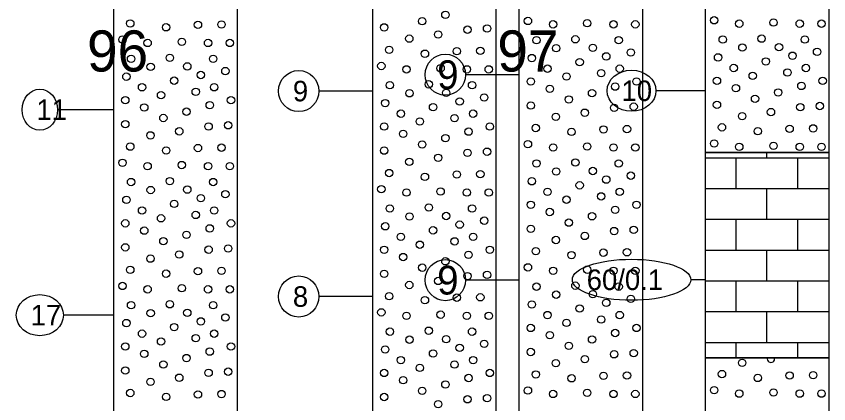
# Model space of a CAD drawing. Extents: x 2345490 to 2436403, y 465165 to 573888.
# Drawn here: x 2389896.8 to 2390094.5, y 557685.8 to 557780.1 of the extents above; entities that cross this region are included whole.
import ezdxf

# ---------------------------------------------------------------- set-up
doc = ezdxf.new("R2010")
doc.units = 0
for name, color, linetype in [('Old_Level_1', 7, 'Continuous'), ('Prop Road Sect_ Boring - Material (Outline)', 7, 'Continuous'), ('Prop Road Sect_ Boring - Peripheral (SPT Oval + Leader)', 7, 'Continuous'), ('Prop Road Sect_ Boring - Peripheral (SPT Tx)', 7, 'Continuous')]:
    doc.layers.add(name, color=color, linetype=linetype)

msp = doc.modelspace()

# ---------------------------------------------------------------- linework, layer by layer
at = {"layer": 'Prop Road Sect_ Boring - Material (Outline)'}
for p, q in [((2390064.5425, 557745.6425), (2390094.51256, 557745.6425)), ((2390072.01251, 557738.14968), (2390072.01251, 557745.6425)), ((2390079.51253, 557745.6425), (2390079.51253, 557746.92666)), ((2390087.01254, 557738.14968), (2390087.01254, 557745.6425)), ((2390094.5275, 557745.6425), (2390094.5425, 557745.6425)), ((2390064.5425, 557738.14968), (2390094.51256, 557738.14968)), ((2390079.51253, 557730.65687), (2390079.51253, 557738.14968)), ((2390094.5275, 557738.14968), (2390094.5425, 557738.14968)), ((2390064.5425, 557730.65687), (2390094.51256, 557730.65687)), ((2390072.01251, 557726.91166), (2390072.01251, 557730.65687)), ((2390087.01254, 557726.91166), (2390087.01254, 557730.65687)), ((2390094.5275, 557730.65687), (2390094.5425, 557730.65687)), ((2390072.01251, 557723.15031), (2390072.01251, 557726.89672)), ((2390087.01254, 557723.15031), (2390087.01254, 557726.89672)), ((2390064.5425, 557723.15031), (2390094.51256, 557723.15031)), ((2390079.51253, 557715.6575), (2390079.51253, 557723.15031)), ((2390094.5275, 557723.15031), (2390094.5425, 557723.15031)), ((2390064.5425, 557715.6575), (2390094.51256, 557715.6575)), ((2390072.01251, 557708.16468), (2390072.01251, 557715.6575)), ((2390087.01254, 557708.16468), (2390087.01254, 557715.6575)), ((2390094.5275, 557715.6575), (2390094.5425, 557715.6575)), ((2390064.5425, 557708.16468), (2390094.51256, 557708.16468)), ((2390079.51253, 557700.67187), (2390079.51253, 557708.16468)), ((2390094.5275, 557708.16468), (2390094.5425, 557708.16468)), ((2390064.5425, 557700.67187), (2390094.51256, 557700.67187)), ((2390072.01251, 557696.92666), (2390072.01251, 557700.67187)), ((2390087.01254, 557696.92666), (2390087.01254, 557700.67187)), ((2390094.5275, 557700.67187), (2390094.5425, 557700.67187))]:
    msp.add_line(p, q, dxfattribs=at)
for points in [[(2389983.5425, 557845.85303), (2390013.5425, 557845.85303), (2390013.5425, 557645.85303), (2389983.5425, 557645.85303)], [(2389920.5425, 557842.314), (2389950.5425, 557842.314), (2389950.5425, 557592.314), (2389920.5425, 557592.314)], [(2390064.5425, 557811.92666), (2390094.5425, 557811.92666), (2390094.5425, 557746.92666), (2390064.5425, 557746.92666)], [(2390019.2285, 557796.83938), (2390049.2285, 557796.83938), (2390049.2285, 557596.83938), (2390019.2285, 557596.83938)], [(2390064.5425, 557746.92666), (2390094.5425, 557746.92666), (2390094.5425, 557696.92666), (2390064.5425, 557696.92666)], [(2390064.5425, 557696.92666), (2390094.5425, 557696.92666), (2390094.5425, 557596.92666), (2390064.5425, 557596.92666)]]:
    msp.add_lwpolyline(points, close=True, dxfattribs=at)
for centre in [(2390001.24558, 557780.39438), (2389924.55055, 557778.32033), (2389941.02058, 557777.97533), (2389946.75059, 557778.06533), (2389995.60556, 557778.84938), (2390021.33154, 557778.9157), (2390027.45156, 557778.0907), (2390035.76157, 557778.3607), (2390042.16659, 557778.0907), (2390047.4766, 557778.0907), (2390066.64554, 557779.07798), (2390072.76556, 557778.25298), (2390081.07557, 557778.52298), (2390087.48059, 557778.25298), (2390092.7906, 557778.25298), (2389933.26557, 557777.37533), (2389986.33555, 557777.34937), (2390006.61559, 557776.79437), (2390011.3856, 557777.07937), (2389922.64554, 557774.39032), (2389992.45556, 557774.61937), (2389999.47557, 557775.60937), (2390023.42542, 557774.22536), (2390032.87723, 557774.45721), (2390043.42155, 557774.22536), (2390068.73942, 557774.38764), (2390078.19123, 557774.6195), (2390088.73555, 557774.38764), (2389928.76556, 557773.56532), (2389937.07557, 557773.83532), (2389943.48059, 557773.56532), (2389948.7906, 557773.56532), (2390028.20437, 557772.27605), (2390037.11379, 557772.38214), (2390073.51837, 557772.43833), (2390082.42779, 557772.54443), (2389987.55055, 557771.88936), (2389996.26557, 557770.94436), (2390004.02058, 557771.54436), (2390009.75059, 557771.63436), (2390040.39658, 557770.29074), (2390046.38159, 557771.25074), (2390067.60555, 557770.04803), (2390085.71058, 557770.45303), (2390091.69559, 557771.41303), (2389924.73942, 557769.69998), (2389934.19123, 557769.93184), (2389944.73555, 557769.69998), (2389985.64554, 557767.95935), (2390022.29155, 557769.88574), (2390033.92653, 557768.90402), (2390079.24053, 557769.06631), (2389929.51837, 557767.75067), (2389938.42779, 557767.85677), (2389947.69559, 557766.72537), (2389991.76556, 557767.13435), (2390000.07557, 557767.40435), (2390006.48059, 557767.13435), (2390011.7906, 557767.13435), (2390026.10155, 557767.30574), (2390039.16658, 557766.21073), (2390043.66659, 557767.30574), (2390071.41555, 557767.46802), (2390084.48058, 557766.37302), (2390088.98059, 557767.46802), (2389923.60555, 557765.36037), (2389935.24053, 557764.37865), (2389941.71058, 557765.76537), (2390022.02155, 557764.17073), (2390030.72156, 557765.40073), (2390047.7466, 557764.17073), (2390067.33555, 557764.33301), (2390076.03556, 557765.56302), (2390093.0606, 557764.33301), (2389927.41555, 557762.78036), (2389944.98059, 557762.78036), (2389987.73942, 557763.26901), (2389997.19123, 557763.50087), (2390007.73555, 557763.26901), (2390026.64156, 557762.40073), (2390042.57159, 557762.94073), (2390071.95556, 557762.56301), (2390087.88559, 557763.10301), (2389932.03556, 557760.87536), (2389940.48058, 557761.68536), (2389992.51837, 557761.3197), (2390001.42779, 557761.4258), (2390010.69559, 557760.2944), (2390036.93158, 557761.36572), (2390082.24558, 557761.52801), (2389923.33555, 557759.64535), (2389943.88559, 557758.41535), (2389949.0606, 557759.64535), (2389986.60555, 557758.9294), (2390004.71058, 557759.3344), (2390022.02155, 557758.32072), (2390031.29156, 557759.82072), (2390067.33555, 557758.483), (2390076.60556, 557759.98301), (2390092.3856, 557758.213), (2389927.95556, 557757.87535), (2389938.24558, 557756.84035), (2389990.41555, 557756.34939), (2389998.24053, 557757.94768), (2390007.98059, 557756.34939), (2390035.16157, 557756.58071), (2390042.30159, 557757.76572), (2390047.0716, 557758.05072), (2390080.47557, 557756.743), (2390087.61559, 557757.928), (2389932.60556, 557755.29535), (2389995.03556, 557754.44439), (2390003.48058, 557755.25439), (2390028.14156, 557755.59071), (2390073.45556, 557755.753), (2389923.33555, 557753.79534), (2389943.61559, 557753.24034), (2389948.3856, 557753.52534), (2389986.33555, 557753.21438), (2390012.0606, 557753.21438), (2390023.23655, 557752.86071), (2390039.70658, 557752.51571), (2390045.43659, 557752.60571), (2390068.55055, 557753.02299), (2390085.02058, 557752.67799), (2390090.75059, 557752.76799), (2389929.45556, 557751.06534), (2389936.47557, 557752.05534), (2389990.95556, 557751.44438), (2390001.24558, 557750.40938), (2390006.88559, 557751.98438), (2390031.95157, 557751.9157), (2390077.26557, 557752.07799), (2389924.55055, 557748.33533), (2389995.60556, 557748.86438), (2390021.33154, 557748.9307), (2390035.76157, 557748.3757), (2390066.64554, 557749.09298), (2390072.76556, 557748.26798), (2390081.07557, 557748.53798), (2390087.48059, 557748.26798), (2390092.7906, 557748.26798), (2389933.26557, 557747.39033), (2389941.02058, 557747.99033), (2389946.75059, 557748.08033), (2389986.33555, 557747.36437), (2390006.61559, 557746.80937), (2390011.3856, 557747.09437), (2390027.45156, 557748.1057), (2390042.16659, 557748.1057), (2390047.4766, 557748.1057), (2389922.64554, 557744.40532), (2389992.45556, 557744.63437), (2389999.47557, 557745.62437), (2390023.42542, 557744.24036), (2390032.87723, 557744.47221), (2390043.42155, 557744.24036), (2389928.76556, 557743.58032), (2389937.07557, 557743.85032), (2389943.48059, 557743.58032), (2389948.7906, 557743.58032), (2390028.20437, 557742.29105), (2390037.11379, 557742.39714), (2389987.55055, 557741.90436), (2389996.26557, 557740.95936), (2390004.02058, 557741.55936), (2390009.75059, 557741.64936), (2390040.39658, 557740.30574), (2390046.38159, 557741.26574), (2389924.73942, 557739.71498), (2389934.19123, 557739.94684), (2389944.73555, 557739.71498), (2390022.29155, 557739.90074), (2390033.92653, 557738.91902), (2389929.51837, 557737.76567), (2389938.42779, 557737.87177), (2389947.69559, 557736.74037), (2389985.64554, 557737.97435), (2389991.76556, 557737.14935), (2390000.07557, 557737.41935), (2390006.48059, 557737.14935), (2390011.7906, 557737.14935), (2390026.10155, 557737.32074), (2390043.66659, 557737.32074), (2389923.60555, 557735.37537), (2389935.24053, 557734.39365), (2389941.71058, 557735.78037), (2390030.72156, 557735.41573), (2390039.16658, 557736.22573), (2389927.41555, 557732.79536), (2389944.98059, 557732.79536), (2389987.73942, 557733.28401), (2389997.19123, 557733.51587), (2390007.73555, 557733.28401), (2390022.02155, 557734.18573), (2390026.64156, 557732.41573), (2390042.57159, 557732.95573), (2390047.7466, 557734.18573), (2389932.03556, 557730.89036), (2389940.48058, 557731.70036), (2389992.51837, 557731.3347), (2390001.42779, 557731.4408), (2390036.93158, 557731.38072), (2389923.33555, 557729.66035), (2389943.88559, 557728.43035), (2389949.0606, 557729.66035), (2389986.60555, 557728.9444), (2390004.71058, 557729.3494), (2390010.69559, 557730.3094), (2390031.29156, 557729.83572), (2389927.95556, 557727.89035), (2389938.24558, 557726.85535), (2389998.24053, 557727.96268), (2390022.02155, 557728.33572), (2390035.16157, 557726.59571), (2390042.30159, 557727.78072), (2390047.0716, 557728.06572), (2389932.60556, 557725.31035), (2389990.41555, 557726.36439), (2389995.03556, 557724.45939), (2390003.48058, 557725.26939), (2390007.98059, 557726.36439), (2390028.14156, 557725.60571), (2389923.33555, 557723.81034), (2389943.61559, 557723.25534), (2389948.3856, 557723.54034), (2389986.33555, 557723.22938), (2390012.0606, 557723.22938), (2390023.23655, 557722.87571), (2390039.70658, 557722.53071), (2390045.43659, 557722.62071), (2389929.45556, 557721.08034), (2389936.47557, 557722.07034), (2389990.95556, 557721.45938), (2390006.88559, 557721.99938), (2390031.95157, 557721.9307), (2389995.60556, 557718.87938), (2390001.24558, 557720.42438), (2390021.33154, 557718.9457), (2389924.55055, 557718.35033), (2389933.26557, 557717.40533), (2389941.02058, 557718.00533), (2389946.75059, 557718.09533), (2389986.33555, 557717.37937), (2390006.61559, 557716.82437), (2390011.3856, 557717.10937), (2390027.45156, 557718.1207), (2390035.76157, 557718.3907), (2390042.16659, 557718.1207), (2390047.4766, 557718.1207), (2389992.45556, 557714.64937), (2389999.47557, 557715.63937), (2389922.64554, 557714.42032), (2389928.76556, 557713.59532), (2389937.07557, 557713.86532), (2389943.48059, 557713.59532), (2389948.7906, 557713.59532), (2390023.42542, 557714.25536), (2390032.87723, 557714.48721), (2390043.42155, 557714.25536), (2389987.55055, 557711.91936), (2389996.26557, 557710.97436), (2390004.02058, 557711.57436), (2390009.75059, 557711.66436), (2390028.20437, 557712.30605), (2390037.11379, 557712.41214), (2390046.38159, 557711.28074), (2389924.73942, 557709.72998), (2389934.19123, 557709.96184), (2389944.73555, 557709.72998), (2390022.29155, 557709.91574), (2390033.92653, 557708.93402), (2390040.39658, 557710.32074), (2389929.51837, 557707.78067), (2389938.42779, 557707.88677), (2389947.69559, 557706.75537), (2389985.64554, 557707.98935), (2389991.76556, 557707.16435), (2390000.07557, 557707.43435), (2390006.48059, 557707.16435), (2390011.7906, 557707.16435), (2390026.10155, 557707.33574), (2390043.66659, 557707.33574), (2389923.60555, 557705.39037), (2389941.71058, 557705.79537), (2390030.72156, 557705.43073), (2390039.16658, 557706.24073), (2389927.41555, 557702.81036), (2389935.24053, 557704.40865), (2389944.98059, 557702.81036), (2389987.73942, 557703.29901), (2389997.19123, 557703.53087), (2390007.73555, 557703.29901), (2390022.02155, 557704.20073), (2390042.57159, 557702.97073), (2390047.7466, 557704.20073), (2389932.03556, 557700.90536), (2389940.48058, 557701.71536), (2389992.51837, 557701.3497), (2390001.42779, 557701.4558), (2390026.64156, 557702.43073), (2390036.93158, 557701.39572), (2389923.33555, 557699.67535), (2389949.0606, 557699.67535), (2389986.60555, 557698.9594), (2390004.71058, 557699.3644), (2390010.69559, 557700.3244), (2390031.29156, 557699.85072), (2389927.95556, 557697.90535), (2389938.24558, 557696.87035), (2389943.88559, 557698.44535), (2389998.24053, 557697.97768), (2390022.02155, 557698.35072), (2390042.30159, 557697.79572), (2390047.0716, 557698.08072), (2389932.60556, 557695.32535), (2389990.41555, 557696.37939), (2390003.48058, 557695.28439), (2390007.98059, 557696.37939), (2390028.14156, 557695.62071), (2390035.16157, 557696.61071), (2390073.45556, 557695.708), (2389923.33555, 557693.82534), (2389943.61559, 557693.27034), (2389948.3856, 557693.55534), (2389986.33555, 557693.24438), (2389995.03556, 557694.47439), (2390012.0606, 557693.24438), (2390023.23655, 557692.89071), (2390068.55055, 557692.97799), (2389929.45556, 557691.09534), (2389936.47557, 557692.08534), (2389990.95556, 557691.47438), (2390006.88559, 557692.01438), (2390031.95157, 557691.9457), (2390039.70658, 557692.54571), (2390045.43659, 557692.63571), (2390077.26557, 557692.03299), (2390085.02058, 557692.63299), (2390090.75059, 557692.72299), (2389995.60556, 557688.89438), (2390001.24558, 557690.43938), (2390021.33154, 557688.9607), (2390066.64554, 557689.04798), (2389924.55055, 557688.36533), (2389933.26557, 557687.42033), (2389941.02058, 557688.02033), (2389946.75059, 557688.11033), (2389986.33555, 557687.39437), (2390011.3856, 557687.12437), (2390027.45156, 557688.1357), (2390035.76157, 557688.4057), (2390042.16659, 557688.1357), (2390047.4766, 557688.1357), (2390072.76556, 557688.22298), (2390081.07557, 557688.49298), (2390087.48059, 557688.22298), (2390092.7906, 557688.22298), (2389999.47557, 557685.65437), (2390006.61559, 557686.83937)]:
    msp.add_circle(centre, 0.9, dxfattribs=at)
msp.add_arc((2390080.47557, 557696.698), 0.9, 165.2816814, 14.7183186, dxfattribs=at)
at = {"layer": 'Prop Road Sect_ Boring - Peripheral (SPT Oval + Leader)'}
for p, q in [((2390019.2285, 557765.83938), (2390006.14582, 557765.83938)), ((2389983.5425, 557761.85303), (2389970.45982, 557761.85303)), ((2390064.5425, 557761.92666), (2390052.48344, 557761.92666)), ((2389920.5425, 557757.314), (2389906.86927, 557757.314)), ((2390019.2285, 557715.83938), (2390006.14582, 557715.83938)), ((2390064.5425, 557715.92666), (2390060.94801, 557715.92666)), ((2389983.5425, 557711.85303), (2389970.45982, 557711.85303)), ((2389920.5425, 557707.314), (2389908.28659, 557707.314))]:
    msp.add_line(p, q, dxfattribs=at)
for centre, major_axis, ratio in [((2390001.2285, 557765.83938), (0, 5), 0.983464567), ((2390046.5425, 557761.92666), (5.94094, 0), 0.841616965), ((2389965.5425, 557761.85303), (0, 5), 0.983464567), ((2389902.5425, 557757.314), (0, 5), 0.865354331), ((2390001.2285, 557715.83938), (0, 5), 0.983464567), ((2390046.5425, 557715.92666), (14.40551, 0), 0.347089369), ((2389965.5425, 557711.85303), (0, 5), 0.983464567), ((2389902.5425, 557707.314), (5.74409, 0), 0.870459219)]:
    msp.add_ellipse(centre, major_axis=major_axis, ratio=ratio, dxfattribs=at)

# ---------------------------------------------------------------- texts
at = {"layer": 'Old_Level_1'}
for s, p in [('96', (2389914.0275, 557766.613)), ('97', (2390013.885, 557766.613))]:
    msp.add_text(s, height=10.000001, dxfattribs=at).set_placement(p)
at = {"layer": 'Prop Road Sect_ Boring - Peripheral (SPT Tx)'}
for s, height, p in [('9', 7, (2389999.24425, 557762.33938)), ('9', 5, (2389964.12518, 557759.35303)), ('10', 5, (2390044.10156, 557759.42666)), ('11', 5, (2389901.71573, 557754.814)), ('9', 7, (2389999.24425, 557712.33938)), ('60/0.1', 5, (2390035.63699, 557713.42666)), ('8', 5, (2389964.12518, 557709.35303)), ('17', 5, (2389900.29841, 557704.814))]:
    msp.add_text(s, height=height, dxfattribs=at).set_placement(p)

doc.saveas('drawing.dxf')
